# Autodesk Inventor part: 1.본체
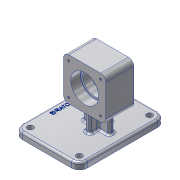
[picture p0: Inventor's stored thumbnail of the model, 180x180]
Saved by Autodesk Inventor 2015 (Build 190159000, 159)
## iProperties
Created: 2020-11
Part Number: 1.본체
Material: 알루미늄 6061
Document SubType Name: Modeling
Designer: pc-04
Density: 2.7 g/cm^3
Appearance: 알루미늄 - 평지
Mass: 683.441 g
Surface Area: 544.674 cm^2
Volume: 253.126 cm^3
Author: pc-04
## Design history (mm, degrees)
sketch "스케치1"
  geometry: L1 (-65, -36)-(65, -36); L2 (65, -36)-(65, 62); L3 (65, 62)-(-65, 62); L4 (-65, 62)-(-65, -36); 1 further point
  constraints: 8 end point, 2 parallel, 1 horizontal, 1 perpendicular
  dimensions: "d0" = 130 distance of L2.end L3.end; "d1" = 98 distance of L1.end L2.end; "d2" = 62 distance from line of point (0, 0) L3; "d3" = 65 distance from line of point (0, 0) L2
extrude "돌출1" new body sketch "스케치1" distance "d4" = 10; taper "d5" = 0 deg
fillet "모깎기1" dims "d6" = 12
sketch "스케치2"
  geometry: L1 (53, -36)-(-53, -36) reference; L2 (-65, -24)-(-65, 50) reference; L3 (-53, 62)-(53, 62) reference; L4 (65, 50)-(65, -24) reference; A1 r 12 centre (53, -24) between (53, -36) and (65, -24) reference; A2 r 12 centre (-53, -24) between (-65, -24) and (-53, -36) reference; A3 r 12 centre (-53, 50) between (-53, 62) and (-65, 50) reference; A4 r 12 centre (53, 50) between (65, 50) and (53, 62) reference; 1 further point
hole "구멍1" sketch "스케치2" at (-53, 50), (-53, -24), (53, -24), (53, 50) diameter "d7" = 9; stored, may be unused: countersink angle "d11" = 90 deg, drill point angle "d13" = 118 deg; dims "d8" = 6, "d9" = 4, "d10" = 2, "d12" = 8
node "작업 평면1"
sketch "스케치3"
  geometry: L1 (21, -32)-(-21, -32); L2 (-21, -32)-(-21, 32); L3 (-21, 32)-(21, 32); L4 (21, 32)-(21, -32); L5 (21, -32)-(-21, 32); L6 (-21, -32)-(21, 32); 1 further point
  constraints: 12 end point, 2 midpoint, 2 parallel, 1 horizontal, 1 perpendicular
  dimensions: "d15" = 42 distance of L2.end L3.end; "d16" = 64 distance of L1.end L2.end
extrude "돌출2" join sketch "스케치3" stored distance "d17" = 64; taper "d18" = 0 deg
sketch "스케치4"
  geometry: L1 (-28, 94)-(-28, -4) reference; L2 (-28, -4)-(-38, -4) reference; L3 (-38, -4)-(-38, 94) reference; L4 (-38, 94)-(-28, 94) reference; L5 (64, 64)-(64, 0) reference; L6 (64, 0)-(0, 0) reference; L7 (0, 0)-(0, 64) reference; L8 (0, 64)-(64, 64) reference; 1 further point
  node "절단 모서리 투영2"
sketch "스케치5"
  geometry: L1 (21, 102)-(21, 38) reference; L2 (21, 70)-(-21, 70); L3 (-21, 38)-(-21, 102) reference; L4 (21, 70)-(6, 70); L5 (6, 70)-(6, 91); L6 (6, 91)-(21, 91); L7 (21, 91)-(21, 70); L8 (6, 70)-(-6, 70); L9 (-6, 70)-(-6, 88); L10 (-6, 88)-(6, 88); L11 (6, 88)-(6, 70); L12 (-6, 70)-(-21, 70); L13 (-21, 70)-(-21, 91); L14 (-21, 91)-(-6, 91); L15 (-6, 91)-(-6, 70); 2 further points
  constraints: 26 end point, 6 parallel, 3 horizontal, 3 midpoint, 3 perpendicular, 2 point on line
  dimensions: "d19" = 15 distance of L5.end L6.end; "d20" = 15 distance of L13.end L14.end; "d21" = 42 diameter of L6 L2; "d22" = 36 diameter of L10 L8
revolve "회전1" sketch "스케치5" stored, may be unused: angle "d23" = 90 deg
fillet "모깎기2" dims "d24" = 8
sketch "스케치7"
  geometry: L1 (-17, 4)-(17, 4); L2 (17, 4)-(17, -4); L3 (17, -4)-(-17, -4); L4 (-17, -4)-(-17, 4); L5 (-4, 20)-(4, 20); L6 (4, 20)-(4, -20); L7 (4, -20)-(-4, -20); L8 (-4, -20)-(-4, 20); 5 further points
  constraints: 16 end point, 4 midpoint, 4 parallel, 2 horizontal, 2 horizontal alignment, 2 perpendicular, 2 vertical alignment
  dimensions: "d25" = 8 distance between parallel lines of L8 L6; "d26" = 8 distance between parallel lines of L3 L1; "d27" = 34 distance between parallel lines of L4 L2; "d28" = 40 distance between parallel lines of L5 L7
extrude "돌출3" join sketch "스케치7" stored distance "d29" = 64; taper "d30" = 0 deg
fillet "모깎기3" dims "d31" = 3
fillet "모깎기4" dims "d32" = 3
fillet "모깎기5" dims "d33" = 0.3
sketch "스케치8"
  geometry: L1 (95, 86)-(102, 86) reference; L2 (102, 86)-(102, -12) reference; L3 (102, -12)-(95, -12) reference; L4 (92, -9)-(92, 83) reference; L5 (64, 48)-(64, 0) reference; L6 (56, -8)-(8, -8) reference; L7 (0, 0)-(0, 48) reference; L8 (8, 56)-(56, 56) reference; C1 r 21 at (32, 24) reference; C2 r 21 at (32, 24) reference; A1 r 3 centre (95, 83) between (95, 86) and (92, 83) reference; A2 r 3 centre (95, -9) between (92, -9) and (95, -12) reference; A3 r 8 centre (56, 0) between (56, -8) and (64, 0) reference; A4 r 8 centre (8, 0) between (0, 0) and (8, -8) reference; A5 r 8 centre (8, 48) between (8, 56) and (0, 48) reference; A6 r 8 centre (56, 48) between (64, 48) and (56, 56) reference; 1 further point
hole "구멍2" sketch "스케치8" at (8, 0), (8, 48), (56, 48), (56, 0) diameter "d34" = 3.242; stored, may be unused: countersink angle "d38" = 90 deg, drill point angle "d40" = 118 deg; dims "d35" = 8, "d36" = 4, "d37" = 2, "d39" = 10
sketch "스케치9"
  geometry: L1 (65, -24)-(65, 50) reference; L2 (53, 62)-(-53, 62) reference; 2 further points
  constraints: 1 other
  dimensions: "d41" = 65 distance from line of point (0, 52) L1; "d42" = 10 distance from line of point (0, 52) L2
feature "엠보싱1" sketch "스케치9" dims "d0" = 130, "d1" = 98, "d2" = 62, "d3" = 65, "d15" = 42, "d16" = 64, "d43" = 0.5, "d44" = 0
node "솔리드1"
mirror "대칭1"
node "절단 모서리 투영1"
node "절단 모서리 투영4"
